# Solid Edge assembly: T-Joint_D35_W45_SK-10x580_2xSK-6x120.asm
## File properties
Author: fknapp
Template: iso metric assembly.asm
Last saved by: fknapp
Revision: 15
Application: Solid Edge
Username: fknapp
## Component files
T-Joint_D35_W45.par
SK Schraube 6x120_ohne_Gewinde.par
SK Schraube 10x580_ohne_Gewinde_22042020.par
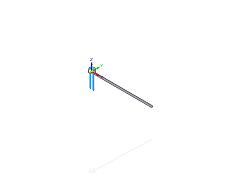
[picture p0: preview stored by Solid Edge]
